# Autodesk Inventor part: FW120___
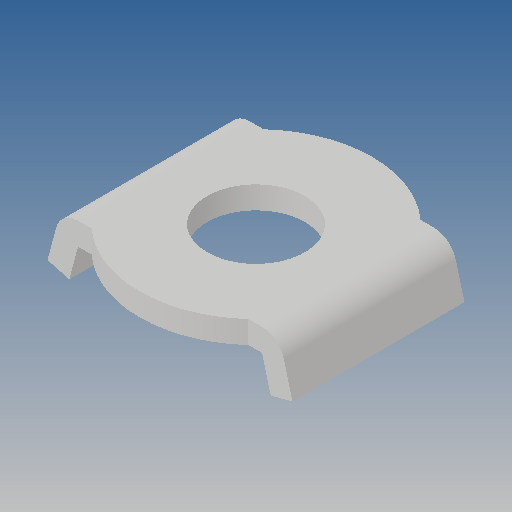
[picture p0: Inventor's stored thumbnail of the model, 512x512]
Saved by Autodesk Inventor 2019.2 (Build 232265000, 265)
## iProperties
Created: 2010-06
Part Number: FW120___
Material: Ogólny
Document SubType Name: Modeling
Designer: CADENGINEERING4
Density: 1 g/cm^3
Appearance: Domyślna
Author: CADENGINEERING4
Revision Number: ANY
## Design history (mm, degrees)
feature "NONE"
node "Bryła1"
